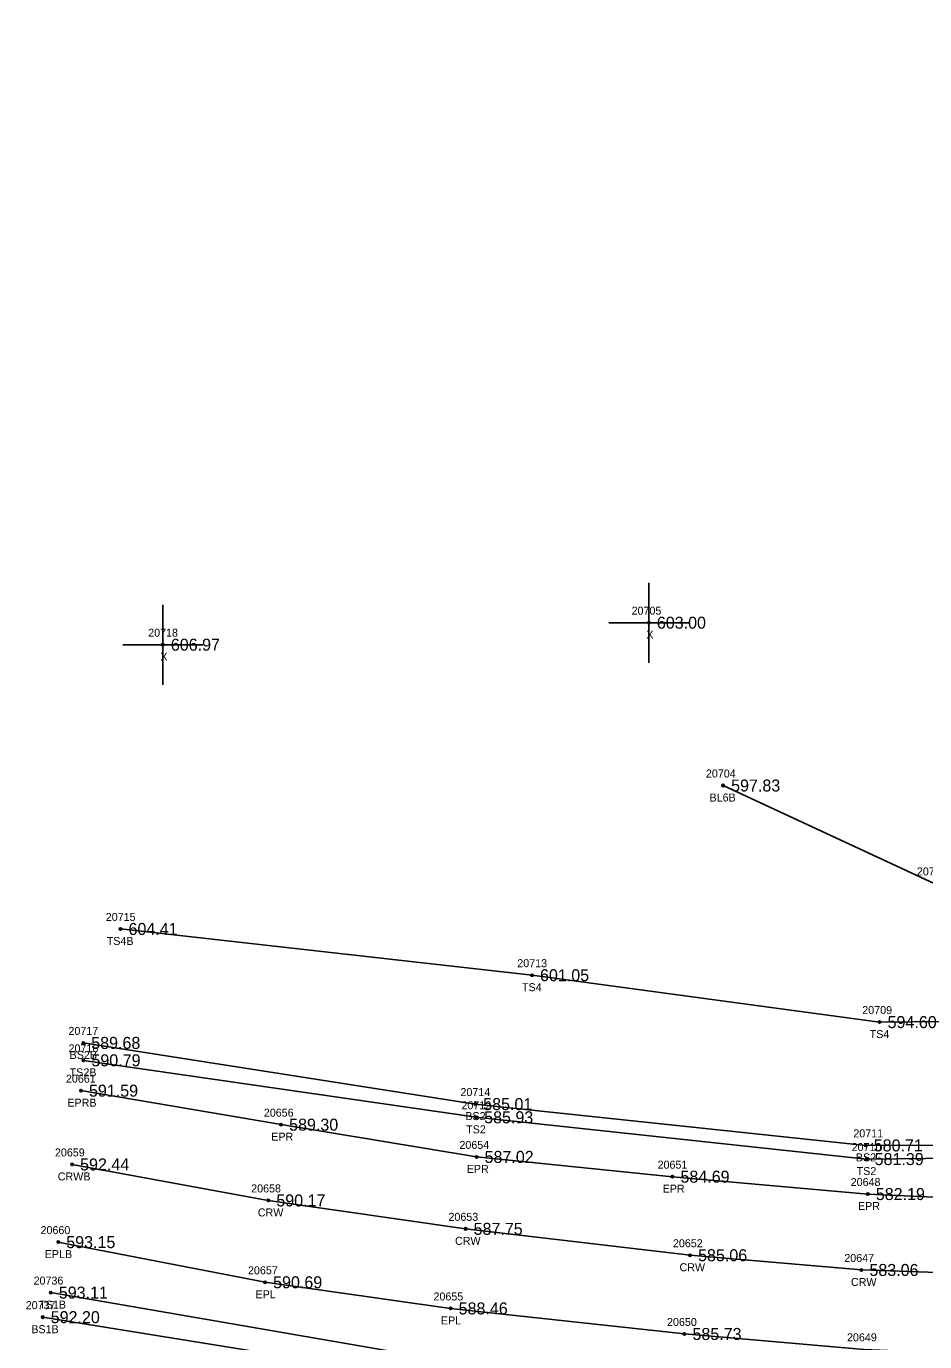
# Model space of a CAD drawing. Extents: x 1540443 to 1541844, y 887157 to 888162.
# Drawn here: x 1540460.7 to 1540572.9, y 887546.6 to 887711 of the extents above; entities that cross this region are included whole.
import ezdxf

# ---------------------------------------------------------------- set-up
doc = ezdxf.new("R2010")
doc.units = 0
for name, color, linetype in [('RD_DTM_BkLn1', 7, 'Continuous'), ('RD_DTM_BkLn2', 7, 'Continuous'), ('RD_DTM_BkLn_txCode', 7, 'Continuous'), ('RD_EX_Misc', 7, 'Continuous'), ('RD_EX_Misc_txCode', 7, 'Continuous'), ('RD_EX_Road', 7, 'Continuous'), ('RD_EX_Road_txCode', 7, 'Continuous'), ('RD_EX_TX_Misc_ELEV', 7, 'Continuous'), ('RD_EX_TX_Road_ELEV', 7, 'Continuous'), ('RD_HC_Survey_ELEV', 7, 'Continuous'), ('RD_HC_Survey_txCode', 7, 'Continuous'), ('RD_SMD_Locator', 7, 'Continuous')]:
    doc.layers.add(name, color=color, linetype=linetype)

msp = doc.modelspace()

# ---------------------------------------------------------------- linework, layer by layer
at = {"layer": 'RD_DTM_BkLn1'}
for points in [[(1541126.44, 887673.83), (1541099.94, 887665.81), (1541052.06, 887651.29), (1541003.93, 887637.63), (1540955.85, 887623.48), (1540907.97, 887609.13), (1540859.88, 887595.48), (1540836.31, 887588.86), (1540811.54, 887582.34), (1540783.96, 887575.59), (1540763.17, 887570.39), (1540738.15, 887565.52), (1540714.18, 887561.19), (1540687.63, 887557.81), (1540664.59, 887555.61), (1540640.72, 887554.4), (1540614.88, 887554.02), (1540589.98, 887554.69), (1540565.01, 887555.56), (1540543.6, 887557.4), (1540515.55, 887560.7), (1540490.9, 887564.25), (1540466.38, 887568.75)], [(1540643.14, 887595.88), (1540623.77, 887600.42), (1540574.1, 887603.87), (1540547.73, 887616.11)]]:
    msp.add_lwpolyline(points, dxfattribs=at)
at = {"layer": 'RD_DTM_BkLn2'}
for points in [[(1541125.73, 887711), (1541094.52, 887702.99), (1541086.54, 887695.93), (1541048.87, 887683.66), (1540995.75, 887663.85), (1540948.75, 887649.66), (1540899.3, 887637.78), (1540852.09, 887622.25), (1540804.6, 887608.33), (1540757.89, 887594.74), (1540710.97, 887581.88), (1540663.03, 887573.83), (1540613.52, 887571.27), (1540565.55, 887571.13), (1540516.75, 887576.29), (1540467.77, 887583.94)], [(1541121.11, 887687.12), (1541116.34, 887691.41), (1541100.71, 887685.78), (1541045.17, 887674.13), (1540997.29, 887658.19), (1540949.92, 887645.1), (1540900.33, 887634.17), (1540852.81, 887620.54), (1540805.55, 887604.61), (1540758.2, 887592.6), (1540711.88, 887580.02), (1540663.85, 887571.28), (1540613.62, 887569.93), (1540565.66, 887569.42), (1540516.87, 887574.64), (1540467.8, 887581.76)], [(1540960.58, 887575.27), (1540958.57, 887598.03), (1540949.34, 887601.53), (1540912.42, 887588.35), (1540865.58, 887574.46), (1540822.62, 887563.37), (1540767.41, 887547.91), (1540718.66, 887535.26), (1540668.13, 887523.76), (1540649.26, 887523.14), (1540607.24, 887534.95), (1540564.64, 887539.95), (1540513.61, 887544.12), (1540463.72, 887552.73)], [(1540632.82, 887590.49), (1540608.35, 887586.94), (1540567.28, 887586.54), (1540523.85, 887592.4), (1540472.43, 887598.18)], [(1540960.58, 887575.27), (1540955.45, 887594.2), (1540950.03, 887596.51), (1540913.42, 887584.06), (1540866.75, 887567.94), (1540825.46, 887557.08), (1540769.44, 887540.76), (1540737.8, 887532.98), (1540709.87, 887528.84), (1540668.36, 887521.72), (1540649.18, 887520.9), (1540606.9, 887532.51), (1540564.07, 887536.98), (1540513.03, 887541.52), (1540462.71, 887549.66)]]:
    msp.add_lwpolyline(points, dxfattribs=at)
at = {"layer": 'RD_EX_Misc'}
for p, q in [((1540538.45, 887631.46), (1540538.45, 887641.46)), ((1540477.72, 887628.71), (1540477.72, 887638.71)), ((1540533.45, 887636.46), (1540543.45, 887636.46)), ((1540472.72, 887633.71), (1540482.72, 887633.71))]:
    msp.add_line(p, q, dxfattribs=at)
at = {"layer": 'RD_EX_Road'}
for points in [[(1541123.73, 887682.83), (1541097.11, 887675.72), (1541048.24, 887661.15), (1541001.64, 887647.51), (1540952.42, 887633.12), (1540904.06, 887618.5), (1540857.24, 887604.78), (1540833.63, 887598.38), (1540808.59, 887591.31), (1540783.7, 887584.16), (1540761.05, 887578.97), (1540736.42, 887574.18), (1540712.73, 887570.56), (1540686.82, 887567.49), (1540663.33, 887565.48), (1540639.94, 887564.35), (1540615, 887563.38), (1540590.61, 887563.9), (1540565.81, 887565.05), (1540541.4, 887567.22), (1540516.92, 887569.69), (1540492.5, 887573.72), (1540467.49, 887577.97)], [(1541128.99, 887664.81), (1541102.04, 887656.79), (1541055.37, 887642.78), (1541004.6, 887628.06), (1540958.93, 887614.62), (1540910.77, 887599.96), (1540863.12, 887586.35), (1540837, 887578.35), (1540814.37, 887572.63), (1540785.6, 887565.57), (1540765.56, 887561), (1540743.15, 887555.32), (1540714.84, 887552.19), (1540688.66, 887548.15), (1540665.15, 887545.04), (1540640.91, 887544.2), (1540614.99, 887544.1), (1540590.77, 887544.52), (1540565.35, 887545.64), (1540542.9, 887547.56), (1540513.68, 887550.75), (1540490.5, 887554.02), (1540464.65, 887559.04)]]:
    msp.add_lwpolyline(points, dxfattribs=at)
at = {"layer": 'RD_SMD_Locator'}
for centre in [(1540538.45, 887636.46), (1540477.72, 887633.71), (1540547.73, 887616.11), (1540472.43, 887598.18), (1540523.85, 887592.4), (1540567.28, 887586.54), (1540467.77, 887583.94), (1540467.8, 887581.76), (1540467.49, 887577.97), (1540516.75, 887576.29), (1540516.87, 887574.64), (1540492.5, 887573.72), (1540565.55, 887571.13), (1540516.92, 887569.69), (1540565.66, 887569.42), (1540466.38, 887568.75), (1540541.4, 887567.22), (1540490.9, 887564.25), (1540565.81, 887565.05), (1540515.55, 887560.7), (1540464.65, 887559.04), (1540543.6, 887557.4), (1540565.01, 887555.56), (1540463.72, 887552.73), (1540490.5, 887554.02), (1540462.71, 887549.66), (1540513.68, 887550.75), (1540542.9, 887547.56)]:
    msp.add_circle(centre, 0.15, dxfattribs=at)

# ---------------------------------------------------------------- texts
at = {"layer": 'RD_DTM_BkLn_txCode'}
for s, p in [('20704', (1540545.58, 887617.11)), ('BL6B', (1540546.03, 887614.11)), ('20703', (1540571.94, 887604.87)), ('20715', (1540470.59, 887599.18)), ('TS4B', (1540470.71, 887596.18)), ('20713', (1540522.01, 887593.4)), ('TS4', (1540522.6, 887590.4)), ('20709', (1540565.12, 887587.54)), ('20717', (1540465.93, 887584.94)), ('TS4', (1540566.04, 887584.54)), ('20716', (1540465.94, 887582.76)), ('BS2B', (1540466.07, 887581.94)), ('TS2B', (1540466.08, 887579.76)), ('20714', (1540514.91, 887577.29)), ('20712', (1540515.03, 887575.64)), ('BS2', (1540515.52, 887574.29)), ('TS2', (1540515.62, 887572.64)), ('20711', (1540564, 887572.13)), ('20710', (1540563.79, 887570.42)), ('BS2', (1540564.32, 887569.13)), ('TS2', (1540564.42, 887567.42)), ('20736', (1540461.57, 887553.73)), ('20737', (1540460.59, 887550.66)), ('TS1B', (1540462.28, 887550.73)), ('BS1B', (1540461.29, 887547.66))]:
    msp.add_text(s, height=1, dxfattribs=at).set_placement(p)
at = {"layer": 'RD_EX_Misc_txCode'}
for s, p in [('20705', (1540536.29, 887637.46)), ('20718', (1540475.89, 887634.71)), ('X', (1540538.13, 887634.46)), ('X', (1540477.41, 887631.71))]:
    msp.add_text(s, height=1, dxfattribs=at).set_placement(p)
at = {"layer": 'RD_EX_Road_txCode'}
for s, p in [('20661', (1540465.61, 887578.97)), ('EPRB', (1540465.79, 887575.97)), ('20656', (1540490.34, 887574.72)), ('EPR', (1540491.27, 887571.72)), ('20654', (1540514.78, 887570.69)), ('20651', (1540539.54, 887568.22)), ('EPR', (1540515.69, 887567.69)), ('EPR', (1540540.17, 887565.22)), ('20648', (1540563.67, 887566.05)), ('EPR', (1540564.58, 887563.05)), ('20660', (1540462.44, 887560.04)), ('EPLB', (1540462.97, 887557.04)), ('20657', (1540488.36, 887555.02)), ('EPL', (1540489.3, 887552.02)), ('20655', (1540511.54, 887551.75)), ('EPL', (1540512.47, 887548.75)), ('20650', (1540540.72, 887548.56)), ('20649', (1540563.21, 887546.64))]:
    msp.add_text(s, height=1, dxfattribs=at).set_placement(p)
at = {"layer": 'RD_EX_TX_Misc_ELEV'}
for s, p in [('603.00', (1540539.45, 887635.71)), ('606.97', (1540478.72, 887632.96)), ('597.83', (1540548.73, 887615.36)), ('604.41', (1540473.43, 887597.43)), ('601.05', (1540524.85, 887591.65)), ('594.60', (1540568.28, 887585.79)), ('589.68', (1540468.77, 887583.19)), ('590.79', (1540468.8, 887581.01)), ('585.01', (1540517.75, 887575.54)), ('585.93', (1540517.87, 887573.89)), ('580.71', (1540566.55, 887570.38)), ('581.39', (1540566.66, 887568.67)), ('593.11', (1540464.72, 887551.98)), ('592.20', (1540463.71, 887548.91))]:
    msp.add_text(s, height=1.5, dxfattribs=at).set_placement(p)
at = {"layer": 'RD_EX_TX_Road_ELEV'}
for s, p in [('591.59', (1540468.49, 887577.22)), ('589.30', (1540493.5, 887572.97)), ('587.02', (1540517.92, 887568.94)), ('584.69', (1540542.4, 887566.47)), ('582.19', (1540566.81, 887564.3)), ('593.15', (1540465.65, 887558.29)), ('590.69', (1540491.5, 887553.27)), ('588.46', (1540514.68, 887550)), ('585.73', (1540543.9, 887546.81))]:
    msp.add_text(s, height=1.5, dxfattribs=at).set_placement(p)
at = {"layer": 'RD_HC_Survey_ELEV'}
for s, p in [('592.44', (1540467.38, 887568)), ('590.17', (1540491.9, 887563.5)), ('587.75', (1540516.55, 887559.95)), ('585.06', (1540544.6, 887556.65)), ('583.06', (1540566.01, 887554.81))]:
    msp.add_text(s, height=1.5, dxfattribs=at).set_placement(p)
at = {"layer": 'RD_HC_Survey_txCode'}
for s, p in [('20659', (1540464.24, 887569.75)), ('CRWB', (1540464.59, 887566.75)), ('20658', (1540488.76, 887565.25)), ('CRW', (1540489.59, 887562.25)), ('20653', (1540513.41, 887561.7)), ('CRW', (1540514.23, 887558.7)), ('20652', (1540541.46, 887558.4)), ('CRW', (1540542.28, 887555.4)), ('20647', (1540562.87, 887556.56)), ('CRW', (1540563.7, 887553.56))]:
    msp.add_text(s, height=1, dxfattribs=at).set_placement(p)

doc.saveas('drawing.dxf')
